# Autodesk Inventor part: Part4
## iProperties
Shininess: 77.0
Length Units: 11269
Angle Units: 11279
Time Units: 11290
Mass Units: 11283
Length Display Precision: 3
Angle Display Precision: 2
Created: 2002-01
Part Number: Part4
Document SubType Name: Modeling
Designer: ***
Density: 0.0
Volumn: 0.0
Area: 0.0
PropertySet Name: Model Information
Control State: 0
Master: False
Checked Out: False
Author: ***
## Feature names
1. Extrusion1
2. Extrusion2
